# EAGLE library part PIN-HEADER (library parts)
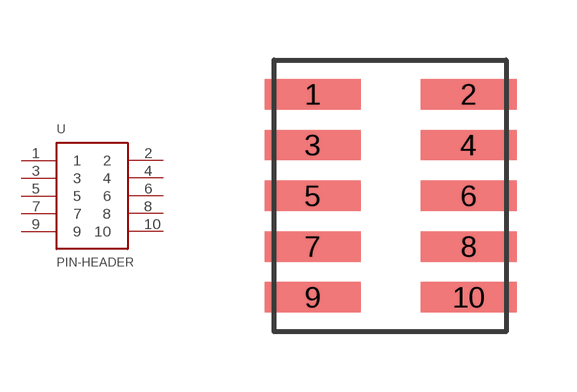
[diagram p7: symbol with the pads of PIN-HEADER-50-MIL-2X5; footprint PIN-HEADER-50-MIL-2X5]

Designator prefix -

## PIN-HEADER  [PIN-HEADER-50-MIL-2X5]
1  1
2  2
3  3
4  4
5  5
6  6
7  7
8  8
9  9
10  10

## Footprint PIN-HEADER-50-MIL-2X5 (pad centres in mm)
smd 2.4 x 0.76: 1 -2.54,2.54; 2 1.36,2.54; 3 -2.54,1.27; 4 1.36,1.27; 5 -2.54,0; 6 1.36,0; 7 -2.54,-1.27; 8 1.36,-1.27; 9 -2.54,-2.54; 10 1.36,-2.54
